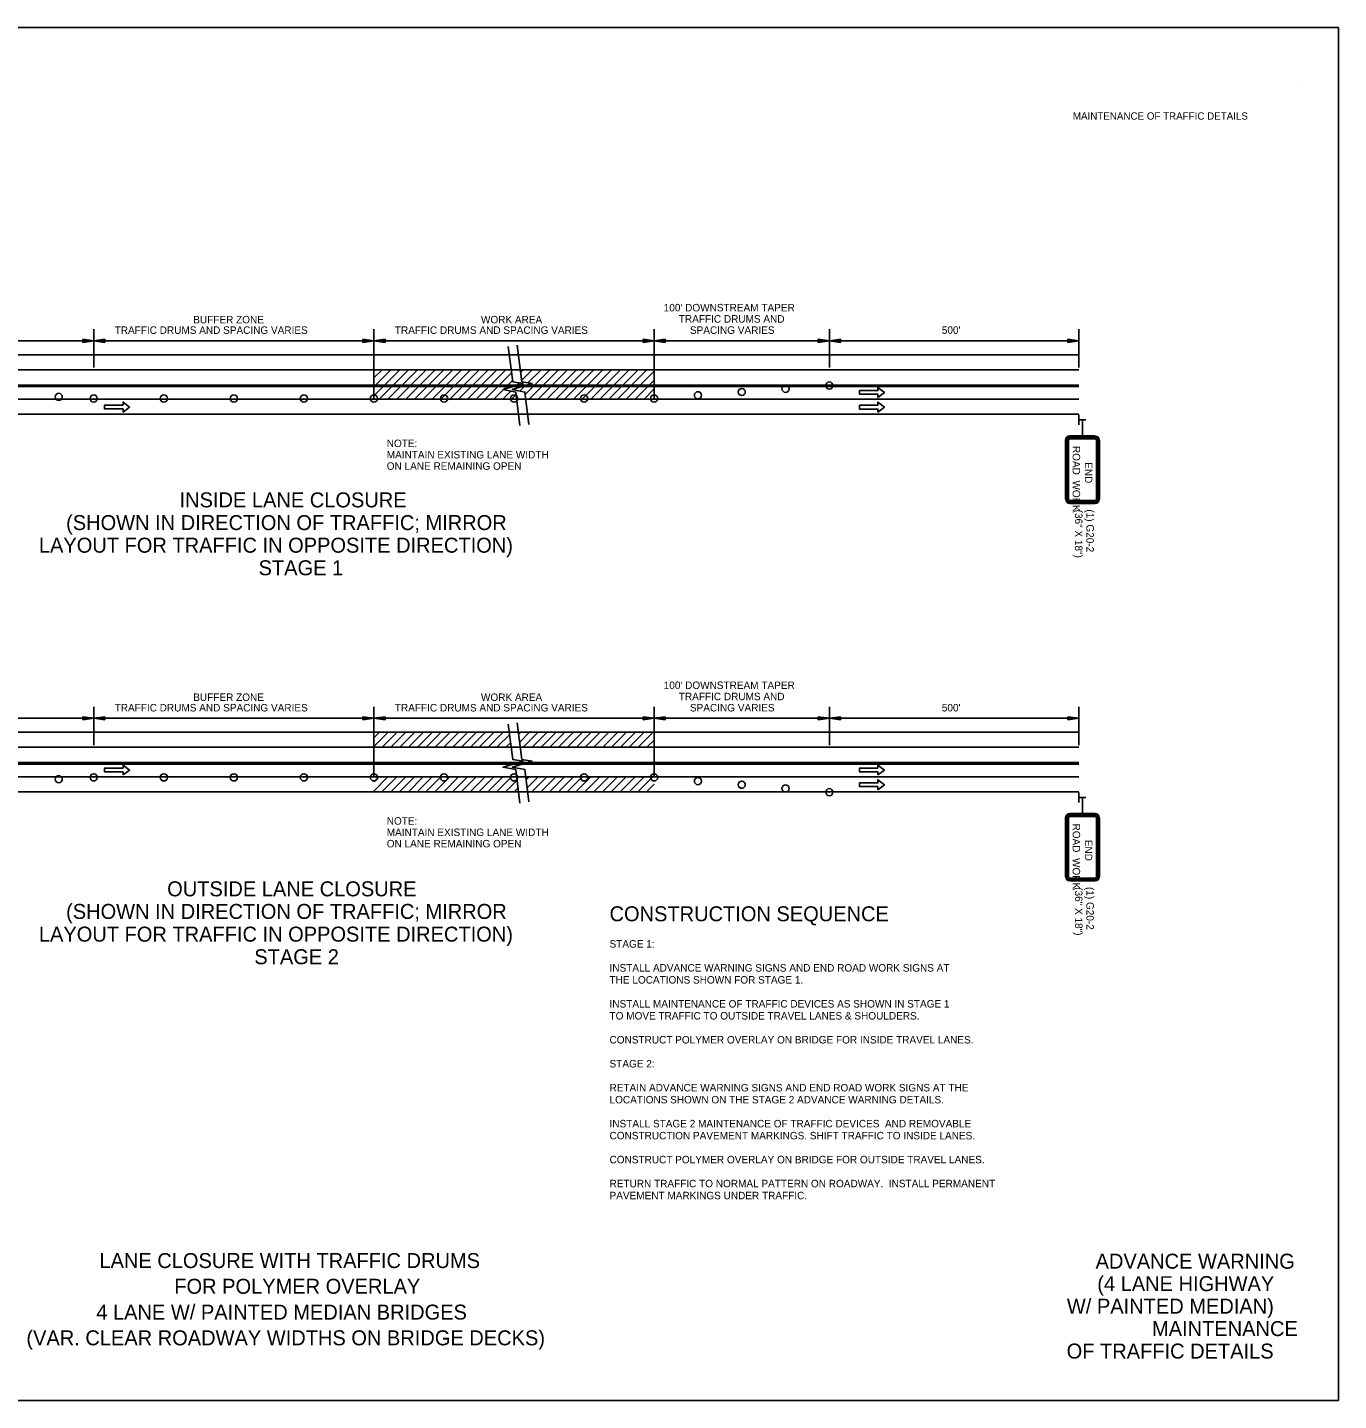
# Model space of a CAD drawing. Extents: x 1930579 to 1938013, y 596452 to 597673.
# Drawn here: x 1936962 to 1938013, y 596573 to 597673 of the extents above; entities that cross this region are included whole.
import ezdxf

# ---------------------------------------------------------------- set-up
doc = ezdxf.new("R2010")
doc.units = 0
for name, color, linetype in [('Default', 7, 'Continuous'), ('P_TC_Signs_Temporary', 7, 'Continuous'), ('R_Border', 7, 'Continuous'), ('R_Striping', 7, 'Continuous'), ('S_AREA_CALC', 7, 'Continuous')]:
    doc.layers.add(name, color=color, linetype=linetype)

msp = doc.modelspace()

# ---------------------------------------------------------------- linework, layer by layer
at = {"layer": 'Default'}
for p, q in [((1937015.5, 597431.7), (1937015.5, 597401)), ((1937240, 597431.7), (1937240, 597375.6)), ((1937464.5, 597431.7), (1937464.5, 597375.6)), ((1937604.9, 597431.7), (1937604.9, 597401)), ((1937804.9, 597431.7), (1937804.9, 597401)), ((1937015.5, 597422.4), (1936791, 597422.4)), ((1937015.5, 597422.4), (1937006.7, 597423.7)), ((1937006.7, 597423.7), (1937006.7, 597421.1)), ((1937006.7, 597421.1), (1937015.5, 597422.4)), ((1937015.5, 597422.4), (1937024.4, 597423.7)), ((1937240, 597422.4), (1937015.5, 597422.4)), ((1937024.4, 597421.1), (1937015.5, 597422.4)), ((1937024.4, 597423.7), (1937024.4, 597421.1)), ((1937231.2, 597421.1), (1937231.2, 597423.7)), ((1937231.2, 597423.7), (1937240, 597422.4)), ((1937240, 597422.4), (1937231.2, 597421.1)), ((1937248.9, 597423.7), (1937240, 597422.4)), ((1937464.5, 597422.4), (1937240, 597422.4)), ((1937240, 597422.4), (1937248.9, 597421.1)), ((1937248.9, 597421.1), (1937248.9, 597423.7)), ((1937455.7, 597421.1), (1937455.7, 597423.7)), ((1937455.7, 597423.7), (1937464.5, 597422.4)), ((1937464.5, 597422.4), (1937455.7, 597421.1)), ((1937473.4, 597423.7), (1937464.5, 597422.4)), ((1937604.9, 597422.4), (1937464.5, 597422.4)), ((1937464.5, 597422.4), (1937473.4, 597421.1)), ((1937473.4, 597421.1), (1937473.4, 597423.7)), ((1937596, 597421.1), (1937596, 597423.7)), ((1937596, 597423.7), (1937604.9, 597422.4)), ((1937604.9, 597422.4), (1937596, 597421.1)), ((1937613.7, 597423.7), (1937604.9, 597422.4)), ((1937804.9, 597422.4), (1937604.9, 597422.4)), ((1937604.9, 597422.4), (1937613.7, 597421.1)), ((1937613.7, 597421.1), (1937613.7, 597423.7)), ((1937796, 597421.1), (1937796, 597423.7)), ((1937796, 597423.7), (1937804.9, 597422.4)), ((1937804.9, 597422.4), (1937796, 597421.1)), ((1937804.9, 597411.2), (1936452.7, 597411.2)), ((1937804.9, 597399.2), (1936452.7, 597399.2)), ((1937240, 597385.5), (1937253.7, 597399.2)), ((1937240, 597392.6), (1937246.6, 597399.2)), ((1937240.2, 597378.6), (1937260.7, 597399.2)), ((1937244.2, 597375.6), (1937267.8, 597399.2)), ((1937251.3, 597375.6), (1937274.9, 597399.2)), ((1937258.4, 597375.6), (1937282, 597399.2)), ((1937265.5, 597375.6), (1937289, 597399.2)), ((1937272.5, 597375.6), (1937296.1, 597399.2)), ((1937279.6, 597375.6), (1937303.2, 597399.2)), ((1937286.7, 597375.6), (1937310.2, 597399.2)), ((1937293.7, 597375.6), (1937317.3, 597399.2)), ((1937300.8, 597375.6), (1937324.4, 597399.2)), ((1937307.9, 597375.6), (1937331.5, 597399.2)), ((1937315, 597375.6), (1937338.5, 597399.2)), ((1937322, 597375.6), (1937345.6, 597399.2)), ((1937357.6, 597397.1), (1937359.7, 597399.2)), ((1937357.6, 597397.1), (1937359.7, 597399.2)), ((1937358.4, 597390.8), (1937366.8, 597399.2)), ((1937361.2, 597379.4), (1937380.9, 597399.2)), ((1937363.4, 597388.7), (1937373.9, 597399.2)), ((1937364.5, 597375.6), (1937388, 597399.2)), ((1937371.5, 597375.6), (1937395.1, 597399.2)), ((1937378.6, 597375.6), (1937402.2, 597399.2)), ((1937385.7, 597375.6), (1937409.2, 597399.2)), ((1937392.7, 597375.6), (1937416.3, 597399.2)), ((1937399.8, 597375.6), (1937423.4, 597399.2)), ((1937406.9, 597375.6), (1937430.4, 597399.2)), ((1937413.9, 597375.6), (1937437.5, 597399.2)), ((1937421, 597375.6), (1937444.6, 597399.2)), ((1937428.1, 597375.6), (1937451.7, 597399.2)), ((1937435.2, 597375.6), (1937458.7, 597399.2)), ((1937442.2, 597375.6), (1937464.5, 597397.9)), ((1937804.9, 597386.9), (1936452.7, 597386.9)), ((1937329.1, 597375.6), (1937350.4, 597396.9)), ((1937336.2, 597375.6), (1937351.1, 597390.6)), ((1937354.1, 597386.4), (1937356.3, 597388.7)), ((1937449.3, 597375.6), (1937464.5, 597390.8)), ((1937804.9, 597385.8), (1936452.7, 597385.8)), ((1937343.2, 597375.6), (1937349.7, 597382)), ((1937350.3, 597375.6), (1937354, 597379.2)), ((1937350.9, 597383.2), (1937350.9, 597383.3)), ((1937356.8, 597382.1), (1937361, 597386.3)), ((1937456.4, 597375.6), (1937464.5, 597383.8)), ((1937463.4, 597375.6), (1937464.5, 597376.7)), ((1937463.4, 597375.6), (1937464.5, 597376.7)), ((1937804.9, 597375.6), (1936452.7, 597375.6)), ((1937804.9, 597363.6), (1936452.7, 597363.6)), ((1937804.9, 597354.9), (1937804.9, 597362.9)), ((1937805, 597358.9), (1937810.4, 597358.9)), ((1937015.5, 597129.2), (1937015.5, 597098.5)), ((1937240, 597129.2), (1937240, 597073.1)), ((1937464.5, 597129.2), (1937464.5, 597073.1)), ((1937604.9, 597129.2), (1937604.9, 597098.5)), ((1937804.9, 597129.2), (1937804.9, 597098.5)), ((1937015.5, 597119.9), (1936791, 597119.9)), ((1937015.5, 597119.9), (1937006.7, 597121.2)), ((1937006.7, 597121.2), (1937006.7, 597118.6)), ((1937006.7, 597118.6), (1937015.5, 597119.9)), ((1937015.5, 597119.9), (1937024.4, 597121.2)), ((1937240, 597119.9), (1937015.5, 597119.9)), ((1937024.4, 597118.6), (1937015.5, 597119.9)), ((1937024.4, 597121.2), (1937024.4, 597118.6)), ((1937231.2, 597118.6), (1937231.2, 597121.2)), ((1937231.2, 597121.2), (1937240, 597119.9)), ((1937240, 597119.9), (1937231.2, 597118.6)), ((1937248.9, 597121.2), (1937240, 597119.9)), ((1937464.5, 597119.9), (1937240, 597119.9)), ((1937240, 597119.9), (1937248.9, 597118.6)), ((1937248.9, 597118.6), (1937248.9, 597121.2)), ((1937455.7, 597118.6), (1937455.7, 597121.2)), ((1937455.7, 597121.2), (1937464.5, 597119.9)), ((1937464.5, 597119.9), (1937455.7, 597118.6)), ((1937473.4, 597121.2), (1937464.5, 597119.9)), ((1937604.9, 597119.9), (1937464.5, 597119.9)), ((1937464.5, 597119.9), (1937473.4, 597118.6)), ((1937473.4, 597118.6), (1937473.4, 597121.2)), ((1937596, 597118.6), (1937596, 597121.2)), ((1937596, 597121.2), (1937604.9, 597119.9)), ((1937604.9, 597119.9), (1937596, 597118.6)), ((1937613.7, 597121.2), (1937604.9, 597119.9)), ((1937804.9, 597119.9), (1937604.9, 597119.9)), ((1937604.9, 597119.9), (1937613.7, 597118.6)), ((1937613.7, 597118.6), (1937613.7, 597121.2)), ((1937796, 597118.6), (1937796, 597121.2)), ((1937796, 597121.2), (1937804.9, 597119.9)), ((1937804.9, 597119.9), (1937796, 597118.6)), ((1937804.9, 597108.7), (1936452.7, 597108.7)), ((1937240, 597097.2), (1937251.5, 597108.7)), ((1937240, 597104.2), (1937244.5, 597108.7)), ((1937246.6, 597096.7), (1937258.6, 597108.7)), ((1937253.7, 597096.7), (1937265.7, 597108.7)), ((1937260.7, 597096.7), (1937272.7, 597108.7)), ((1937267.8, 597096.7), (1937279.8, 597108.7)), ((1937274.9, 597096.7), (1937286.9, 597108.7)), ((1937282, 597096.7), (1937294, 597108.7)), ((1937289, 597096.7), (1937301, 597108.7)), ((1937296.1, 597096.7), (1937308.1, 597108.7)), ((1937303.2, 597096.7), (1937315.2, 597108.7)), ((1937310.2, 597096.7), (1937322.2, 597108.7)), ((1937317.3, 597096.7), (1937329.3, 597108.7)), ((1937324.4, 597096.7), (1937336.4, 597108.7)), ((1937331.5, 597096.7), (1937343.5, 597108.7)), ((1937338.5, 597096.7), (1937348.8, 597106.9)), ((1937356.1, 597107.1), (1937357.6, 597108.7)), ((1937356.8, 597100.8), (1937364.7, 597108.7)), ((1937359.7, 597096.7), (1937371.7, 597108.7)), ((1937366.8, 597096.7), (1937378.8, 597108.7)), ((1937373.9, 597096.7), (1937385.9, 597108.7)), ((1937380.9, 597096.7), (1937392.9, 597108.7)), ((1937388, 597096.7), (1937400, 597108.7)), ((1937395.1, 597096.7), (1937407.1, 597108.7)), ((1937402.2, 597096.7), (1937414.2, 597108.7)), ((1937409.2, 597096.7), (1937421.2, 597108.7)), ((1937416.3, 597096.7), (1937428.3, 597108.7)), ((1937423.4, 597096.7), (1937435.4, 597108.7)), ((1937430.4, 597096.7), (1937442.4, 597108.7)), ((1937437.5, 597096.7), (1937449.5, 597108.7)), ((1937444.6, 597096.7), (1937456.6, 597108.7)), ((1937451.7, 597096.7), (1937463.7, 597108.7)), ((1937458.7, 597096.7), (1937464.5, 597102.5)), ((1937804.9, 597096.7), (1936452.7, 597096.7)), ((1937345.6, 597096.7), (1937349.6, 597100.6)), ((1937804.9, 597084.4), (1936452.7, 597084.4)), ((1937804.9, 597083.3), (1936452.7, 597083.3)), ((1937350.9, 597080.7), (1937350.9, 597080.7)), ((1937804.9, 597073.1), (1936452.7, 597073.1)), ((1937239.3, 597061.1), (1937251.3, 597073.1)), ((1937240, 597068.9), (1937244.2, 597073.1)), ((1937246.4, 597061.1), (1937258.4, 597073.1)), ((1937253.5, 597061.1), (1937265.5, 597073.1)), ((1937260.5, 597061.1), (1937272.5, 597073.1)), ((1937267.6, 597061.1), (1937279.6, 597073.1)), ((1937274.7, 597061.1), (1937286.7, 597073.1)), ((1937281.7, 597061.1), (1937293.7, 597073.1)), ((1937288.8, 597061.1), (1937300.8, 597073.1)), ((1937295.9, 597061.1), (1937307.9, 597073.1)), ((1937303, 597061.1), (1937315, 597073.1)), ((1937310, 597061.1), (1937322, 597073.1)), ((1937317.1, 597061.1), (1937329.1, 597073.1)), ((1937324.2, 597061.1), (1937336.2, 597073.1)), ((1937331.2, 597061.1), (1937343.2, 597073.1)), ((1937338.3, 597061.1), (1937350.3, 597073.1)), ((1937345.4, 597061.1), (1937354.7, 597070.4)), ((1937362, 597070.6), (1937364.5, 597073.1)), ((1937362.7, 597064.3), (1937371.5, 597073.1)), ((1937366.6, 597061.1), (1937378.6, 597073.1)), ((1937373.7, 597061.1), (1937385.7, 597073.1)), ((1937380.7, 597061.1), (1937392.7, 597073.1)), ((1937387.8, 597061.1), (1937399.8, 597073.1)), ((1937394.9, 597061.1), (1937406.9, 597073.1)), ((1937401.9, 597061.1), (1937413.9, 597073.1)), ((1937409, 597061.1), (1937421, 597073.1)), ((1937416.1, 597061.1), (1937428.1, 597073.1)), ((1937423.2, 597061.1), (1937435.2, 597073.1)), ((1937430.2, 597061.1), (1937442.2, 597073.1)), ((1937437.3, 597061.1), (1937449.3, 597073.1)), ((1937444.4, 597061.1), (1937456.4, 597073.1)), ((1937451.4, 597061.1), (1937464.5, 597074.2)), ((1937463.4, 597073.1), (1937464.5, 597074.2)), ((1937804.9, 597061.1), (1936452.7, 597061.1)), ((1937352.5, 597061.1), (1937355.5, 597064.1)), ((1937458.5, 597061.1), (1937464.5, 597067.1)), ((1937804.9, 597052.4), (1937804.9, 597060.4)), ((1937805, 597056.4), (1937810.4, 597056.4))]:
    msp.add_line(p, q, dxfattribs=at)
for points in [[(1937347.7, 597417.9), (1937351.3, 597389.5), (1937359.5, 597388.1), (1937343.5, 597383.2), (1937353.7, 597381.3), (1937356.9, 597354.5)], [(1937354.9, 597418.8), (1937358.6, 597389.5), (1937366.8, 597388.1), (1937350.8, 597383.2), (1937361, 597381.3), (1937364.1, 597355.4)], [(1937347.7, 597115.3), (1937351.3, 597087), (1937359.5, 597085.6), (1937343.5, 597080.7), (1937353.7, 597078.8), (1937356.9, 597052)], [(1937354.9, 597116.2), (1937358.6, 597087), (1937366.8, 597085.6), (1937350.8, 597080.7), (1937361, 597078.8), (1937364.1, 597052.9)]]:
    msp.add_lwpolyline(points, dxfattribs=at)
for centre in [(1937604.9, 597386.5), (1936987.5, 597377.4), (1937015.5, 597376.1), (1937071.7, 597376.1), (1937127.8, 597376.1), (1937183.9, 597376.1), (1937240, 597376.1), (1937296.2, 597376.1), (1937352.3, 597376.1), (1937408.4, 597376.1), (1937464.5, 597376.1), (1937499.6, 597378.7), (1937534.7, 597381.3), (1937569.8, 597383.9), (1936987.5, 597071.1), (1937015.5, 597072.6), (1937071.7, 597072.6), (1937127.8, 597072.6), (1937183.9, 597072.6), (1937240, 597072.6), (1937296.2, 597072.6), (1937352.3, 597072.6), (1937408.4, 597072.6), (1937464.5, 597072.6), (1937499.6, 597069.6), (1937534.7, 597066.7), (1937569.8, 597063.7), (1937604.9, 597060.7)]:
    msp.add_circle(centre, 2.87, dxfattribs=at)
at = {"layer": 'P_TC_Signs_Temporary'}
for p, q in [((1937817.8, 597346.1), (1937797.6, 597346.1)), ((1937817.8, 597345.2), (1937797.6, 597345.2)), ((1937817.8, 597343.9), (1937797.6, 597343.9)), ((1937794.2, 597342.7), (1937794.2, 597295.5)), ((1937795.1, 597342.7), (1937795.1, 597295.5)), ((1937796.5, 597342.7), (1937796.5, 597295.5)), ((1937819, 597295.5), (1937819, 597342.7)), ((1937820.3, 597295.5), (1937820.3, 597342.7)), ((1937821.2, 597295.5), (1937821.2, 597342.7)), ((1937797.6, 597294.4), (1937817.8, 597294.4)), ((1937797.6, 597293.1), (1937817.8, 597293.1)), ((1937797.6, 597292.1), (1937817.8, 597292.1)), ((1937794.2, 597040.2), (1937794.2, 596993)), ((1937795.1, 597040.2), (1937795.1, 596993)), ((1937796.5, 597040.2), (1937796.5, 596993)), ((1937817.8, 597043.6), (1937797.6, 597043.6)), ((1937817.8, 597042.7), (1937797.6, 597042.7)), ((1937817.8, 597041.3), (1937797.6, 597041.3)), ((1937819, 596993), (1937819, 597040.2)), ((1937820.3, 596993), (1937820.3, 597040.2)), ((1937821.2, 596993), (1937821.2, 597040.2)), ((1937797.6, 596991.8), (1937817.8, 596991.8)), ((1937797.6, 596990.5), (1937817.8, 596990.5)), ((1937797.6, 596989.6), (1937817.8, 596989.6))]:
    msp.add_line(p, q, dxfattribs=at)
for centre, radius, start, end in [((1937797.6, 597342.7), 3.38, 90, 180), ((1937797.6, 597342.7), 2.44, 90, 180), ((1937797.6, 597342.7), 1.13, 90, 180), ((1937817.8, 597342.7), 3.37, 360, 90), ((1937817.8, 597342.7), 2.44, 360, 90), ((1937817.8, 597342.7), 1.13, 360, 90), ((1937797.6, 597295.5), 3.37, 180, 270), ((1937797.6, 597295.5), 2.44, 180, 270), ((1937797.6, 597295.5), 1.13, 180, 270), ((1937817.8, 597295.5), 2.44, 270, 360), ((1937817.8, 597295.5), 1.13, 270, 360), ((1937817.8, 597295.5), 3.38, 270, 360), ((1937797.6, 597040.2), 3.38, 90, 180), ((1937797.6, 597040.2), 2.44, 90, 180), ((1937797.6, 597040.2), 1.13, 90, 180), ((1937817.8, 597040.2), 3.37, 360, 90), ((1937817.8, 597040.2), 2.44, 360, 90), ((1937817.8, 597040.2), 1.13, 360, 90), ((1937797.6, 596993), 3.37, 180, 270), ((1937797.6, 596993), 2.44, 180, 270), ((1937797.6, 596993), 1.13, 180, 270), ((1937817.8, 596993), 2.44, 270, 360), ((1937817.8, 596993), 1.13, 270, 360), ((1937817.8, 596993), 3.38, 270, 360)]:
    msp.add_arc(centre, radius, start, end, dxfattribs=at)
at = {"layer": 'R_Border'}
for p, q in [((1937807.7, 597358.9), (1937807.7, 597346.1)), ((1937807.7, 597056.4), (1937807.7, 597043.6))]:
    msp.add_line(p, q, dxfattribs=at)
at = {"layer": 'R_Striping'}
for points in [[(1937643.8, 597377), (1937649, 597381), (1937643.8, 597385), (1937643.8, 597382.5), (1937629.1, 597382.5), (1937629.1, 597379.5), (1937643.8, 597379.5)], [(1937039, 597365.3), (1937044.2, 597369.3), (1937039, 597373.3), (1937039, 597370.8), (1937024.3, 597370.8), (1937024.3, 597367.8), (1937039, 597367.8)], [(1937643.8, 597365.2), (1937649, 597369.2), (1937643.8, 597373.2), (1937643.8, 597370.7), (1937629.1, 597370.7), (1937629.1, 597367.7), (1937643.8, 597367.7)], [(1937039, 597074.5), (1937044.2, 597078.5), (1937039, 597082.5), (1937039, 597080), (1937024.3, 597080), (1937024.3, 597077), (1937039, 597077)], [(1937643.8, 597074.5), (1937649, 597078.5), (1937643.8, 597082.5), (1937643.8, 597080), (1937629.1, 597080), (1937629.1, 597077), (1937643.8, 597077)], [(1937643.8, 597062.7), (1937649, 597066.7), (1937643.8, 597070.7), (1937643.8, 597068.2), (1937629.1, 597068.2), (1937629.1, 597065.2), (1937643.8, 597065.2)]]:
    msp.add_lwpolyline(points, close=True, dxfattribs=at)
at = {"layer": 'S_AREA_CALC'}
msp.add_line((1937984, 597629.9), (1937984, 597629.9), dxfattribs=at)
msp.add_lwpolyline([(1938012.8, 597673.4), (1936312.8, 597673.4), (1936312.8, 596573.4), (1938012.8, 596573.4)], close=True, dxfattribs=at)

# ---------------------------------------------------------------- texts
at = {"layer": 'Default'}
for s, height, p in [('BUFFER ZONE', 6, (1937095.3, 597436.3)), ('WORK AREA', 6, (1937325.8, 597436.3)), ("100' DOWNSTREAM TAPER", 6, (1937472.2, 597445.9)), ('TRAFFIC DRUMS AND ', 6, (1937484.3, 597436.9)), ('TRAFFIC DRUMS AND SPACING VARIES', 6, (1937032.3, 597427.9)), ('TRAFFIC DRUMS AND SPACING VARIES', 6, (1937256.8, 597427.9)), ('SPACING VARIES', 6, (1937493.2, 597427.9)), ("500'", 6, (1937695, 597427.9)), ('INSIDE LANE CLOSURE', 12, (1937084.3, 597288.9)), ('(SHOWN IN DIRECTION OF TRAFFIC; MIRROR', 12, (1936993.4, 597270.7)), ('LAYOUT FOR TRAFFIC IN OPPOSITE DIRECTION)', 12, (1936971.6, 597252.6)), ('STAGE 1', 12, (1937147.6, 597234.5)), ("100' DOWNSTREAM TAPER", 6, (1937472.2, 597143.4)), ('BUFFER ZONE', 6, (1937095.3, 597133.8)), ('WORK AREA', 6, (1937325.8, 597133.8)), ('TRAFFIC DRUMS AND ', 6, (1937484.3, 597134.4)), ('TRAFFIC DRUMS AND SPACING VARIES', 6, (1937032.3, 597125.4)), ('TRAFFIC DRUMS AND SPACING VARIES', 6, (1937256.8, 597125.4)), ('SPACING VARIES', 6, (1937493.2, 597125.4)), ("500'", 6, (1937695, 597125.4)), ('OUTSIDE LANE CLOSURE', 12, (1937074.4, 596977.3)), ('(SHOWN IN DIRECTION OF TRAFFIC; MIRROR', 12, (1936993.4, 596959.2)), ('LAYOUT FOR TRAFFIC IN OPPOSITE DIRECTION)', 12, (1936971.6, 596941)), ('STAGE 2', 12, (1937144.2, 596922.9)), ('LANE CLOSURE WITH TRAFFIC DRUMS', 12, (1937020.1, 596679.5)), ('FOR POLYMER OVERLAY', 12, (1937080.1, 596658.9)), ('4 LANE W/ PAINTED MEDIAN BRIDGES', 12, (1937017.6, 596638.2)), ('(VAR. CLEAR ROADWAY WIDTHS ON BRIDGE DECKS)', 12, (1936961.6, 596617.6))]:
    msp.add_text(s, height=height, rotation=360, dxfattribs=at).set_placement(p)
at = {"layer": 'P_TC_Signs_Temporary'}
for s, p in [('ROAD  WORK', (1937799.8, 597338.1)), ('END', (1937809.6, 597325.1)), ('ROAD  WORK', (1937799.8, 597035.6)), ('END', (1937809.6, 597022.6))]:
    msp.add_text(s, height=6, rotation=270, dxfattribs=at).set_placement(p)
at = {"layer": 'R_Border'}
for s, height, rotation, p in [('NOTE:', 6, 360, (1937250.3, 597337.2)), ('MAINTAIN EXISTING LANE WIDTH', 6, 360, (1937250.3, 597328.1)), ('ON LANE REMAINING OPEN', 6, 360, (1937250.3, 597319)), ('(36" X 18")', 6, 270, (1937801.7, 597287.1)), ('(1) G20-2', 6, 270, (1937810.8, 597287.3)), ('NOTE:', 6, 360, (1937250.3, 597034.7)), ('MAINTAIN EXISTING LANE WIDTH', 6, 360, (1937250.3, 597025.6)), ('ON LANE REMAINING OPEN', 6, 360, (1937250.3, 597016.5)), ('(36" X 18")', 6, 270, (1937801.7, 596984.6)), ('(1) G20-2', 6, 270, (1937810.8, 596984.8)), ('CONSTRUCTION SEQUENCE', 12, 360, (1937428.8, 596957.3)), ('STAGE 1:', 6, 360, (1937428.8, 596936.2)), ('INSTALL ADVANCE WARNING SIGNS AND END ROAD WORK SIGNS AT', 6, 360, (1937428.8, 596917)), ('THE LOCATIONS SHOWN FOR STAGE 1.', 6, 360, (1937428.8, 596907.4)), ('INSTALL MAINTENANCE OF TRAFFIC DEVICES AS SHOWN IN STAGE 1', 6, 360, (1937428.8, 596888.2)), ('TO MOVE TRAFFIC TO OUTSIDE TRAVEL LANES & SHOULDERS.', 6, 360, (1937428.8, 596878.6)), ('CONSTRUCT POLYMER OVERLAY ON BRIDGE FOR INSIDE TRAVEL LANES.', 6, 360, (1937428.8, 596859.4)), ('STAGE 2:', 6, 360, (1937428.8, 596840.2)), ('RETAIN ADVANCE WARNING SIGNS AND END ROAD WORK SIGNS AT THE', 6, 360, (1937428.8, 596821)), ('LOCATIONS SHOWN ON THE STAGE 2 ADVANCE WARNING DETAILS.', 6, 360, (1937428.8, 596811.4)), ('INSTALL STAGE 2 MAINTENANCE OF TRAFFIC DEVICES  AND REMOVABLE', 6, 360, (1937428.8, 596792.2)), ('CONSTRUCTION PAVEMENT MARKINGS. SHIFT TRAFFIC TO INSIDE LANES.', 6, 360, (1937428.8, 596782.6)), ('CONSTRUCT POLYMER OVERLAY ON BRIDGE FOR OUTSIDE TRAVEL LANES.', 6, 360, (1937428.8, 596763.4)), ('RETURN TRAFFIC TO NORMAL PATTERN ON ROADWAY.  INSTALL PERMANENT', 6, 360, (1937428.8, 596744.2)), ('PAVEMENT MARKINGS UNDER TRAFFIC.', 6, 360, (1937428.8, 596734.6)), ('ADVANCE WARNING', 12, 360, (1937818.2, 596679)), (' (4 LANE HIGHWAY', 12, 360, (1937815.1, 596661)), ('W/ PAINTED MEDIAN)', 12, 360, (1937795.2, 596643)), ('MAINTENANCE ', 12, 360, (1937863.4, 596625)), ('OF TRAFFIC DETAILS', 12, 360, (1937795, 596607))]:
    msp.add_text(s, height=height, rotation=rotation, dxfattribs=at).set_placement(p)
at = {"layer": 'S_AREA_CALC'}
msp.add_text('MAINTENANCE OF TRAFFIC DETAILS', height=5.862, rotation=360, dxfattribs=at).set_placement((1937800, 597599.5))

doc.saveas('drawing.dxf')
